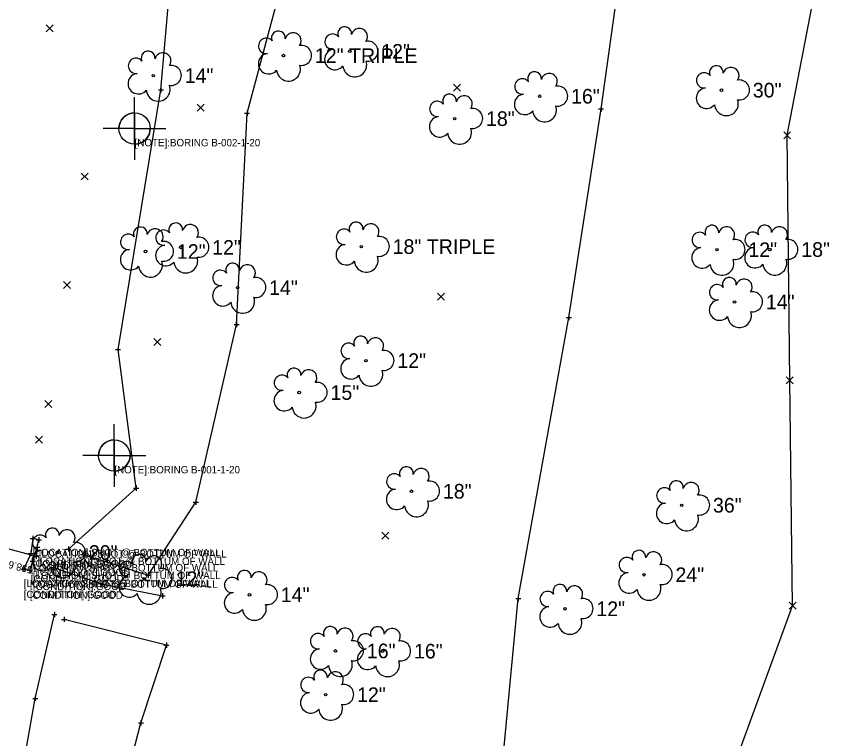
# Model space of a CAD drawing. Extents: x 1380627 to 1381920, y 503402 to 506786.
# Drawn here: x 1381754.6 to 1381912.7, y 504668.1 to 504806.3 of the extents above; entities that cross this region are included whole.
import ezdxf

# ---------------------------------------------------------------- set-up
doc = ezdxf.new("R2010")
doc.units = 0
for name, color, linetype in [('DR_X_Ditch', 7, 'Continuous'), ('DR_X_Elev_Flow', 7, 'Continuous'), ('DR_X_Storm_Sewer', 7, 'Continuous'), ('GT_Project_Soil_Boring', 7, 'Continuous'), ('RD_X_Wall', 7, 'Continuous'), ('SC_Scratch1', 7, 'Continuous'), ('SV_X_Random_Point', 7, 'Continuous'), ('SV_X_Shot_Marker', 7, 'Continuous'), ('SV_X_Terrain_Boundary', 7, 'Continuous'), ('SV_X_Text', 7, 'Continuous'), ('SV_X_Toe_of_Slope', 7, 'Continuous'), ('SV_X_Top_of_Bank', 7, 'Continuous'), ('VG_X_Cells', 7, 'Continuous'), ('VG_X_Text', 7, 'Continuous')]:
    doc.layers.add(name, color=color, linetype=linetype)

msp = doc.modelspace()

# ---------------------------------------------------------------- linework, layer by layer
at = {"layer": 'DR_X_Ditch'}
msp.add_lwpolyline([(1381761.75, 504700.84), (1381771.16, 504697.61), (1381782.6, 504695.43)], dxfattribs=at)
at = {"layer": 'DR_X_Elev_Flow'}
for p, q in [((1381757.89, 504703.01), (1381758.89, 504703.01)), ((1381758.39, 504703.51), (1381758.39, 504702.51)), ((1381758.39, 504703.01), (1381758.39, 504703.01))]:
    msp.add_line(p, q, dxfattribs=at)
at = {"layer": 'DR_X_Storm_Sewer'}
msp.add_line((1381644.11, 504733.11), (1381758.39, 504703.01), dxfattribs=at)
at = {"layer": 'GT_Project_Soil_Boring'}
for p, q in [((1381777.24, 504784.82), (1381777.24, 504790.82)), ((1381777.24, 504787.82), (1381777.24, 504784.82)), ((1381777.24, 504784.82), (1381771.24, 504784.82)), ((1381777.24, 504784.82), (1381774.24, 504784.82)), ((1381777.24, 504784.82), (1381777.24, 504778.82)), ((1381777.24, 504784.82), (1381783.24, 504784.82)), ((1381777.24, 504781.82), (1381777.24, 504784.82)), ((1381777.24, 504784.82), (1381780.24, 504784.82)), ((1381773.36, 504722.25), (1381773.36, 504728.25)), ((1381773.36, 504725.25), (1381773.36, 504722.25)), ((1381773.36, 504722.25), (1381767.36, 504722.25)), ((1381773.36, 504722.25), (1381770.36, 504722.25)), ((1381773.36, 504722.25), (1381773.36, 504716.25)), ((1381773.36, 504722.25), (1381779.37, 504722.25)), ((1381773.36, 504719.25), (1381773.36, 504722.25)), ((1381773.36, 504722.25), (1381776.36, 504722.25))]:
    msp.add_line(p, q, dxfattribs=at)
for centre in [(1381777.24, 504784.82), (1381773.36, 504722.25)]:
    msp.add_circle(centre, 3, dxfattribs=at)
for centre, start, end in [((1381777.24, 504784.82), 90, 180), ((1381777.24, 504784.82), 270, 360), ((1381773.36, 504722.25), 90, 180), ((1381773.36, 504722.25), 270, 360)]:
    msp.add_arc(centre, 3, start, end, dxfattribs=at)
at = {"layer": 'RD_X_Wall'}
msp.add_lwpolyline([(1381757.2, 504700.34), (1381757.78, 504702.02), (1381758.61, 504704.72), (1381758.93, 504706.12), (1381757.76, 504706.4), (1381757.37, 504703.48), (1381756.03, 504700.49)], close=True, dxfattribs=at)
at = {"layer": 'SV_X_Random_Point'}
for p, q in [((1381760.32, 504803.34), (1381761.65, 504804.67)), ((1381760.32, 504804.67), (1381761.65, 504803.34)), ((1381838.26, 504791.99), (1381839.59, 504793.32)), ((1381838.26, 504793.32), (1381839.59, 504791.99)), ((1381789.18, 504788.17), (1381790.52, 504789.51)), ((1381789.18, 504789.51), (1381790.52, 504788.17)), ((1381901.41, 504782.86), (1381902.74, 504784.19)), ((1381901.41, 504784.19), (1381902.74, 504782.86)), ((1381767.01, 504774.98), (1381768.34, 504776.31)), ((1381767.01, 504776.31), (1381768.34, 504774.98)), ((1381763.66, 504754.24), (1381764.99, 504755.57)), ((1381763.66, 504755.57), (1381764.99, 504754.24)), ((1381835.18, 504752), (1381836.51, 504753.34)), ((1381835.18, 504753.34), (1381836.51, 504752)), ((1381780.95, 504743.28), (1381782.28, 504744.62)), ((1381780.95, 504744.62), (1381782.28, 504743.28)), ((1381901.91, 504735.98), (1381903.24, 504737.31)), ((1381901.91, 504737.31), (1381903.24, 504735.98)), ((1381760.05, 504731.43), (1381761.38, 504732.77)), ((1381760.05, 504732.77), (1381761.38, 504731.43)), ((1381758.3, 504724.63), (1381759.63, 504725.96)), ((1381758.3, 504725.96), (1381759.63, 504724.63)), ((1381824.55, 504706.24), (1381825.88, 504707.58)), ((1381824.55, 504707.58), (1381825.88, 504706.24)), ((1381902.44, 504692.84), (1381903.77, 504694.17)), ((1381902.44, 504694.17), (1381903.77, 504692.84))]:
    msp.add_line(p, q, dxfattribs=at)
at = {"layer": 'SV_X_Shot_Marker'}
for p, q in [((1381781.78, 504792.24), (1381782.78, 504792.24)), ((1381782.28, 504792.74), (1381782.28, 504791.74)), ((1381782.28, 504792.24), (1381782.28, 504792.24)), ((1381798.75, 504788.26), (1381798.75, 504787.26)), ((1381865.97, 504788.59), (1381866.97, 504788.59)), ((1381866.47, 504789.09), (1381866.47, 504788.09)), ((1381866.47, 504788.59), (1381866.47, 504788.59)), ((1381798.25, 504787.76), (1381799.25, 504787.76)), ((1381798.75, 504787.76), (1381798.75, 504787.76)), ((1381859.79, 504748.65), (1381860.79, 504748.65)), ((1381860.29, 504749.15), (1381860.29, 504748.15)), ((1381860.29, 504748.65), (1381860.29, 504748.65)), ((1381796.26, 504747.32), (1381797.26, 504747.32)), ((1381796.76, 504747.82), (1381796.76, 504746.82)), ((1381796.76, 504747.32), (1381796.76, 504747.32)), ((1381773.57, 504742.51), (1381774.57, 504742.51)), ((1381774.07, 504743.01), (1381774.07, 504742.01)), ((1381774.07, 504742.51), (1381774.07, 504742.51)), ((1381777.05, 504716.02), (1381778.05, 504716.02)), ((1381777.55, 504716.52), (1381777.55, 504715.52)), ((1381777.55, 504716.02), (1381777.55, 504716.02)), ((1381788.44, 504713.32), (1381789.44, 504713.32)), ((1381788.94, 504713.82), (1381788.94, 504712.82)), ((1381788.94, 504713.32), (1381788.94, 504713.32)), ((1381757.26, 504706.4), (1381758.26, 504706.4)), ((1381757.76, 504706.9), (1381757.76, 504705.9)), ((1381757.76, 504706.4), (1381757.76, 504706.4)), ((1381758.43, 504706.12), (1381759.43, 504706.12)), ((1381758.93, 504706.62), (1381758.93, 504705.62)), ((1381758.93, 504706.12), (1381758.93, 504706.12)), ((1381758.11, 504704.72), (1381759.11, 504704.72)), ((1381758.61, 504705.22), (1381758.61, 504704.22)), ((1381758.61, 504704.72), (1381758.61, 504704.72)), ((1381764.57, 504704.86), (1381764.57, 504703.86)), ((1381756.87, 504703.48), (1381757.87, 504703.48)), ((1381757.37, 504703.98), (1381757.37, 504702.98)), ((1381757.37, 504703.48), (1381757.37, 504703.48)), ((1381764.07, 504704.36), (1381765.07, 504704.36)), ((1381764.57, 504704.36), (1381764.57, 504704.36)), ((1381766.88, 504703.3), (1381767.88, 504703.3)), ((1381767.38, 504703.8), (1381767.38, 504702.8)), ((1381767.38, 504703.3), (1381767.38, 504703.3)), ((1381757.28, 504702.02), (1381758.28, 504702.02)), ((1381757.78, 504702.52), (1381757.78, 504701.52)), ((1381757.78, 504702.02), (1381757.78, 504702.02)), ((1381761.75, 504701.34), (1381761.75, 504700.34)), ((1381755.53, 504700.49), (1381756.53, 504700.49)), ((1381756.03, 504700.99), (1381756.03, 504699.99)), ((1381756.03, 504700.49), (1381756.03, 504700.49)), ((1381756.7, 504700.34), (1381757.7, 504700.34)), ((1381757.2, 504700.84), (1381757.2, 504699.84)), ((1381757.2, 504700.34), (1381757.2, 504700.34)), ((1381761.25, 504700.84), (1381762.25, 504700.84)), ((1381761.75, 504700.84), (1381761.75, 504700.84)), ((1381779.81, 504699.86), (1381779.81, 504698.86)), ((1381771.16, 504698.11), (1381771.16, 504697.11)), ((1381779.31, 504699.36), (1381780.31, 504699.36)), ((1381779.81, 504699.36), (1381779.81, 504699.36)), ((1381770.66, 504697.61), (1381771.66, 504697.61)), ((1381771.16, 504697.61), (1381771.16, 504697.61)), ((1381782.1, 504695.43), (1381783.1, 504695.43)), ((1381782.6, 504695.93), (1381782.6, 504694.93)), ((1381782.6, 504695.43), (1381782.6, 504695.43)), ((1381850.64, 504695.37), (1381850.64, 504694.37)), ((1381850.14, 504694.87), (1381851.14, 504694.87)), ((1381850.64, 504694.87), (1381850.64, 504694.87)), ((1381761.39, 504691.85), (1381762.39, 504691.85)), ((1381761.89, 504692.35), (1381761.89, 504691.35)), ((1381761.89, 504691.85), (1381761.89, 504691.85)), ((1381763.25, 504690.91), (1381764.25, 504690.91)), ((1381763.75, 504691.41), (1381763.75, 504690.41)), ((1381763.75, 504690.91), (1381763.75, 504690.91)), ((1381782.81, 504685.95), (1381783.81, 504685.95)), ((1381783.31, 504686.45), (1381783.31, 504685.45)), ((1381783.31, 504685.95), (1381783.31, 504685.95)), ((1381758.24, 504676.29), (1381758.24, 504675.29)), ((1381757.74, 504675.79), (1381758.74, 504675.79)), ((1381758.24, 504675.79), (1381758.24, 504675.79)), ((1381778.46, 504671.63), (1381778.46, 504670.63)), ((1381777.96, 504671.13), (1381778.96, 504671.13)), ((1381778.46, 504671.13), (1381778.46, 504671.13))]:
    msp.add_line(p, q, dxfattribs=at)
at = {"layer": 'SV_X_Terrain_Boundary'}
msp.add_lwpolyline([(1381633.07, 504590.71), (1381640.41, 504588.23), (1381652.11, 504583.89), (1381663.49, 504580.19), (1381671.46, 504576.88), (1381673.04, 504575.38), (1381691.74, 504593.89), (1381728.42, 504597.15), (1381743.97, 504596.11), (1381756.96, 504593.19), (1381809.7, 504557.46), (1381859.78, 504551.94), (1381857.29, 504586.1), (1381880.18, 504630.82), (1381903.11, 504693.5), (1381902.57, 504736.65), (1381902.08, 504783.53), (1381912.66, 504838.51)], dxfattribs=at)
at = {"layer": 'SV_X_Toe_of_Slope'}
for points in [[(1381764.57, 504704.36), (1381777.55, 504716.02), (1381774.07, 504742.51), (1381782.28, 504792.24), (1381785.73, 504831.46), (1381791.93, 504857.65), (1381796.1, 504892.69), (1381799.39, 504943.01)], [(1381809.7, 504557.46), (1381827.24, 504600.65), (1381846.42, 504650.4), (1381850.64, 504694.87), (1381860.29, 504748.65), (1381866.47, 504788.59), (1381874.56, 504846.72), (1381883.38, 504901.17)], [(1381743.97, 504596.11), (1381750.58, 504632.7), (1381758.24, 504675.79), (1381761.89, 504691.85)]]:
    msp.add_lwpolyline(points, dxfattribs=at)
at = {"layer": 'SV_X_Top_of_Bank'}
for points in [[(1381767.38, 504703.3), (1381779.81, 504699.36), (1381788.94, 504713.32), (1381796.76, 504747.32), (1381798.75, 504787.76), (1381816.59, 504854.3), (1381813.57, 504891.79), (1381822.76, 504937.76)], [(1381756.96, 504593.19), (1381767.53, 504628.92), (1381778.46, 504671.13), (1381783.31, 504685.95), (1381763.75, 504690.91)]]:
    msp.add_lwpolyline(points, dxfattribs=at)
at = {"layer": 'VG_X_Cells'}
for centre in [(1381818.42, 504799.58), (1381805.73, 504798.78), (1381780.82, 504794.95), (1381889.5, 504792.16), (1381854.73, 504791), (1381838.46, 504786.71), (1381779.33, 504761.29), (1381786.08, 504762.07), (1381820.6, 504762.23), (1381888.65, 504761.63), (1381898.77, 504761.67), (1381796.97, 504754.37), (1381892, 504751.64), (1381821.49, 504740.41), (1381808.72, 504734.31), (1381830.22, 504715.42), (1381881.88, 504712.74), (1381762.48, 504703.7), (1381874.7, 504699.44), (1381779.08, 504698.68), (1381799.21, 504695.61), (1381859.57, 504692.93), (1381815.66, 504684.87), (1381824.68, 504684.82), (1381813.79, 504676.49)]:
    msp.add_circle(centre, 0.24, dxfattribs=at)
for centre, radius, start, end in [((1381817.43, 504802.95), 1.32, 354.0047, 205.9741), ((1381820.24, 504802.41), 1.55, 323.83, 165.0376), ((1381804.75, 504802.15), 1.32, 354.0047, 205.9741), ((1381807.56, 504801.61), 1.55, 323.83, 165.0376), ((1381815.11, 504801.45), 1.47, 39.0625, 279.5412), ((1381802.42, 504800.65), 1.47, 39.0625, 279.5412), ((1381821.88, 504799.62), 1.91, 259.1453, 101.4596), ((1381779.83, 504798.32), 1.32, 354.0047, 205.9741), ((1381782.64, 504797.78), 1.55, 323.83, 165.0376), ((1381802.88, 504797.23), 1.97, 96.1722, 320.5737), ((1381809.19, 504798.82), 1.91, 259.1453, 101.4596), ((1381815.56, 504798.04), 1.97, 96.1722, 320.5737), ((1381777.51, 504796.81), 1.47, 39.0625, 279.5412), ((1381819.36, 504796.98), 2.28, 184.9476, 19.4572), ((1381784.28, 504794.98), 1.91, 259.1453, 101.4596), ((1381806.68, 504796.18), 2.28, 184.9476, 19.4572), ((1381888.52, 504795.53), 1.32, 354.0047, 205.9741), ((1381891.33, 504794.99), 1.55, 323.83, 165.0376), ((1381777.96, 504793.4), 1.97, 96.1722, 320.5737), ((1381853.74, 504794.36), 1.32, 354.0047, 205.9741), ((1381856.55, 504793.83), 1.55, 323.83, 165.0376), ((1381886.19, 504794.03), 1.47, 39.0625, 279.5412), ((1381781.76, 504792.34), 2.28, 184.9476, 19.4572), ((1381851.42, 504792.86), 1.47, 39.0625, 279.5412), ((1381858.19, 504791.03), 1.91, 259.1453, 101.4596), ((1381892.96, 504792.2), 1.91, 259.1453, 101.4596), ((1381837.48, 504790.08), 1.32, 354.0047, 205.9741), ((1381851.87, 504789.45), 1.97, 96.1722, 320.5737), ((1381886.65, 504790.62), 1.97, 96.1722, 320.5737), ((1381835.15, 504788.58), 1.47, 39.0625, 279.5412), ((1381840.29, 504789.54), 1.55, 323.83, 165.0376), ((1381890.45, 504789.56), 2.28, 184.9476, 19.4572), ((1381841.92, 504786.75), 1.91, 259.1453, 101.4596), ((1381855.67, 504788.39), 2.28, 184.9476, 19.4572), ((1381835.61, 504785.16), 1.97, 96.1722, 320.5737), ((1381839.41, 504784.11), 2.28, 184.9476, 19.4572), ((1381785.1, 504765.44), 1.32, 354.0047, 205.9741), ((1381787.91, 504764.9), 1.55, 323.83, 165.0376), ((1381819.62, 504765.6), 1.32, 354.0047, 205.9741), ((1381822.43, 504765.06), 1.55, 323.83, 165.0376), ((1381887.67, 504765), 1.32, 354.0047, 205.9741), ((1381890.48, 504764.46), 1.55, 323.83, 165.0376), ((1381897.79, 504765.04), 1.32, 354.0047, 205.9741), ((1381900.6, 504764.5), 1.55, 323.83, 165.0376), ((1381776.02, 504763.15), 1.47, 39.0625, 279.5412), ((1381778.35, 504764.66), 1.32, 354.0047, 205.9741), ((1381781.16, 504764.12), 1.55, 323.83, 165.0376), ((1381782.77, 504763.94), 1.47, 39.0625, 279.5412), ((1381817.29, 504764.1), 1.47, 39.0625, 279.5412), ((1381885.34, 504763.5), 1.47, 39.0625, 279.5412), ((1381895.46, 504763.53), 1.47, 39.0625, 279.5412), ((1381782.79, 504761.33), 1.91, 259.1453, 101.4596), ((1381789.54, 504762.11), 1.91, 259.1453, 101.4596), ((1381824.06, 504762.27), 1.91, 259.1453, 101.4596), ((1381892.11, 504761.67), 1.91, 259.1453, 101.4596), ((1381902.23, 504761.7), 1.91, 259.1453, 101.4596), ((1381776.48, 504759.74), 1.97, 96.1722, 320.5737), ((1381783.23, 504760.53), 1.97, 96.1722, 320.5737), ((1381817.75, 504760.69), 1.97, 96.1722, 320.5737), ((1381885.8, 504760.08), 1.97, 96.1722, 320.5737), ((1381895.92, 504760.12), 1.97, 96.1722, 320.5737), ((1381787.03, 504759.47), 2.28, 184.9476, 19.4572), ((1381821.55, 504759.63), 2.28, 184.9476, 19.4572), ((1381889.6, 504759.03), 2.28, 184.9476, 19.4572), ((1381899.72, 504759.06), 2.28, 184.9476, 19.4572), ((1381780.28, 504758.68), 2.28, 184.9476, 19.4572), ((1381795.99, 504757.74), 1.32, 354.0047, 205.9741), ((1381798.8, 504757.2), 1.55, 323.83, 165.0376), ((1381793.66, 504756.24), 1.47, 39.0625, 279.5412), ((1381800.43, 504754.41), 1.91, 259.1453, 101.4596), ((1381888.69, 504753.5), 1.47, 39.0625, 279.5412), ((1381891.02, 504755.01), 1.32, 354.0047, 205.9741), ((1381893.83, 504754.47), 1.55, 323.83, 165.0376), ((1381794.12, 504752.83), 1.97, 96.1722, 320.5737), ((1381895.46, 504751.67), 1.91, 259.1453, 101.4596), ((1381797.92, 504751.77), 2.28, 184.9476, 19.4572), ((1381889.15, 504750.09), 1.97, 96.1722, 320.5737), ((1381892.95, 504749.03), 2.28, 184.9476, 19.4572), ((1381820.51, 504743.78), 1.32, 354.0047, 205.9741), ((1381823.32, 504743.24), 1.55, 323.83, 165.0376), ((1381818.19, 504742.28), 1.47, 39.0625, 279.5412), ((1381824.96, 504740.45), 1.91, 259.1453, 101.4596), ((1381818.64, 504738.86), 1.97, 96.1722, 320.5737), ((1381805.41, 504736.18), 1.47, 39.0625, 279.5412), ((1381807.74, 504737.68), 1.32, 354.0047, 205.9741), ((1381810.55, 504737.14), 1.55, 323.83, 165.0376), ((1381822.44, 504737.81), 2.28, 184.9476, 19.4572), ((1381812.18, 504734.35), 1.91, 259.1453, 101.4596), ((1381805.87, 504732.76), 1.97, 96.1722, 320.5737), ((1381809.67, 504731.71), 2.28, 184.9476, 19.4572), ((1381826.91, 504717.29), 1.47, 39.0625, 279.5412), ((1381829.24, 504718.79), 1.32, 354.0047, 205.9741), ((1381832.05, 504718.25), 1.55, 323.83, 165.0376), ((1381833.68, 504715.46), 1.91, 259.1453, 101.4596), ((1381880.89, 504716.11), 1.32, 354.0047, 205.9741), ((1381883.7, 504715.57), 1.55, 323.83, 165.0376), ((1381827.37, 504713.88), 1.97, 96.1722, 320.5737), ((1381878.57, 504714.61), 1.47, 39.0625, 279.5412), ((1381885.34, 504712.78), 1.91, 259.1453, 101.4596), ((1381831.17, 504712.82), 2.28, 184.9476, 19.4572), ((1381879.02, 504711.2), 1.97, 96.1722, 320.5737), ((1381882.82, 504710.14), 2.28, 184.9476, 19.4572), ((1381761.49, 504707.07), 1.32, 354.0047, 205.9741), ((1381764.3, 504706.53), 1.55, 323.83, 165.0376), ((1381759.17, 504705.57), 1.47, 39.0625, 279.5412), ((1381765.94, 504703.74), 1.91, 259.1453, 101.4596), ((1381759.62, 504702.15), 1.97, 96.1722, 320.5737), ((1381778.1, 504702.04), 1.32, 354.0047, 205.9741), ((1381780.91, 504701.51), 1.55, 323.83, 165.0376), ((1381873.71, 504702.81), 1.32, 354.0047, 205.9741), ((1381876.52, 504702.27), 1.55, 323.83, 165.0376), ((1381763.42, 504701.1), 2.28, 184.9476, 19.4572), ((1381775.77, 504700.54), 1.47, 39.0625, 279.5412), ((1381871.39, 504701.3), 1.47, 39.0625, 279.5412), ((1381878.16, 504699.48), 1.91, 259.1453, 101.4596), ((1381782.54, 504698.71), 1.91, 259.1453, 101.4596), ((1381798.23, 504698.97), 1.32, 354.0047, 205.9741), ((1381801.04, 504698.44), 1.55, 323.83, 165.0376), ((1381871.84, 504697.89), 1.97, 96.1722, 320.5737), ((1381776.23, 504697.13), 1.97, 96.1722, 320.5737), ((1381795.9, 504697.47), 1.47, 39.0625, 279.5412), ((1381780.03, 504696.07), 2.28, 184.9476, 19.4572), ((1381802.67, 504695.64), 1.91, 259.1453, 101.4596), ((1381858.59, 504696.3), 1.32, 354.0047, 205.9741), ((1381861.4, 504695.76), 1.55, 323.83, 165.0376), ((1381875.64, 504696.83), 2.28, 184.9476, 19.4572), ((1381796.36, 504694.06), 1.97, 96.1722, 320.5737), ((1381856.26, 504694.8), 1.47, 39.0625, 279.5412), ((1381800.16, 504693), 2.28, 184.9476, 19.4572), ((1381856.72, 504691.38), 1.97, 96.1722, 320.5737), ((1381863.03, 504692.97), 1.91, 259.1453, 101.4596), ((1381860.52, 504690.33), 2.28, 184.9476, 19.4572), ((1381814.68, 504688.23), 1.32, 354.0047, 205.9741), ((1381817.49, 504687.7), 1.55, 323.83, 165.0376), ((1381823.7, 504688.19), 1.32, 354.0047, 205.9741), ((1381826.51, 504687.65), 1.55, 323.83, 165.0376), ((1381812.35, 504686.73), 1.47, 39.0625, 279.5412), ((1381821.37, 504686.69), 1.47, 39.0625, 279.5412), ((1381819.12, 504684.9), 1.91, 259.1453, 101.4596), ((1381828.14, 504684.86), 1.91, 259.1453, 101.4596), ((1381812.81, 504683.32), 1.97, 96.1722, 320.5737), ((1381821.83, 504683.27), 1.97, 96.1722, 320.5737), ((1381816.61, 504682.26), 2.28, 184.9476, 19.4572), ((1381825.63, 504682.22), 2.28, 184.9476, 19.4572), ((1381812.81, 504679.86), 1.32, 354.0047, 205.9741), ((1381815.62, 504679.32), 1.55, 323.83, 165.0376), ((1381810.48, 504678.36), 1.47, 39.0625, 279.5412), ((1381817.25, 504676.53), 1.91, 259.1453, 101.4596), ((1381810.94, 504674.95), 1.97, 96.1722, 320.5737), ((1381814.74, 504673.89), 2.28, 184.9476, 19.4572)]:
    msp.add_arc(centre, radius, start, end, dxfattribs=at)

# ---------------------------------------------------------------- texts
at = {"layer": 'SC_Scratch1'}
msp.add_text('598.62', height=1.4, rotation=165.2421, dxfattribs=at).set_placement((1381757.84, 504700.93))
at = {"layer": 'SV_X_Text'}
for s, p in [('[NOTE]:BORING B-002-1-20', (1381777.24, 504781.42)), ('[NOTE]:BORING B-001-1-20', (1381773.36, 504718.85)), ('[LOCATION]:SHOT @ BOTTUM OF WALL', (1381757.76, 504703)), ('[LOCATION]:SHOT @ BOTTUM OF WALL', (1381758.93, 504702.72)), ('[LOCATION]:SHOT @ BOTTUM OF WALL', (1381757.37, 504700.08)), ('[CONDITION]:GOOD', (1381757.76, 504700.9)), ('[LOCATION]:SHOT @ BOTTUM OF WALL', (1381758.61, 504701.32)), ('[CONDITION]:GOOD', (1381758.93, 504700.62)), ('[LOCATION]:SHOT @ BOTTUM OF WALL', (1381757.78, 504698.62)), ('[CONDITION]:GOOD', (1381758.61, 504699.22)), ('[LOCATION]:SHOT @ BOTTUM OF WALL', (1381756.03, 504697.09)), ('[LOCATION]:SHOT @ BOTTUM OF WALL', (1381757.2, 504696.95)), ('[CONDITION]:GOOD', (1381757.37, 504697.98)), ('[CONDITION]:GOOD', (1381757.78, 504696.52)), ('[CONDITION]:GOOD', (1381756.03, 504694.99)), ('[CONDITION]:GOOD', (1381757.2, 504694.84))]:
    msp.add_text(s, height=1.4, dxfattribs=at).set_placement(p)
at = {"layer": 'VG_X_Text'}
for s, p in [('12"', (1381824.42, 504798.18)), ('12" TRIPLE', (1381811.73, 504797.38)), ('14"', (1381786.82, 504793.55)), ('30"', (1381895.5, 504790.76)), ('16"', (1381860.73, 504789.6)), ('18"', (1381844.46, 504785.31)), ('12"', (1381792.08, 504760.67)), ('18" TRIPLE', (1381826.6, 504760.83)), ('12"', (1381894.65, 504760.23)), ('18"', (1381904.77, 504760.27)), ('12"', (1381785.33, 504759.89)), ('14"', (1381802.97, 504752.97)), ('14"', (1381898, 504750.24)), ('12"', (1381827.5, 504739.01)), ('15"', (1381814.72, 504732.91)), ('18"', (1381836.22, 504714.02)), ('36"', (1381887.88, 504711.34)), ('20"', (1381768.48, 504702.3)), ('12"', (1381785.08, 504697.28)), ('24"', (1381880.7, 504698.04)), ('14"', (1381805.21, 504694.21)), ('12"', (1381865.57, 504691.53)), ('16"', (1381821.66, 504683.47)), ('16"', (1381830.68, 504683.42)), ('12"', (1381819.79, 504675.09))]:
    msp.add_text(s, height=2.8, dxfattribs=at).set_placement(p)

doc.saveas('drawing.dxf')
